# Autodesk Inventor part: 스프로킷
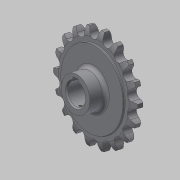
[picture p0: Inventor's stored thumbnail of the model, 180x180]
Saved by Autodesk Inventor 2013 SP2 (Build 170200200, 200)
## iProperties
Created: 2016-03
Part Number: 스프로킷
Material: 강철, 탄소
Document SubType Name: Modeling
Designer: mduedu
Density: 7.87 g/cm^3
Mass: 301.818 g
Surface Area: 124.882 cm^2
Volume: 38.3505 cm^3
Author: mduedu
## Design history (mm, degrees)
sketch "스케치1"
  geometry: L1 (0, 5)-(29.5, 5); L2 (29.5, 5)-(29.5, 4.1); L3 (30, 3.6)-(33.625, 3.6); L4 (40, 2)-(40, 0); L5 (40, 0)-(0, 0); L6 (0, 0)-(0, 5); L7 (0, -5)-(29.5, -5); L8 (29.5, -5)-(29.5, -4.1); L9 (30, -3.6)-(33.625, -3.6); L10 (40, -2)-(40, 0); L11 (0, 0)-(0, -5); A1 r 13.5 centre (33.625, -9.9) between (40, 2) and (33.625, 3.6); A2 r 13.5 centre (33.625, 9.9) between (33.625, -3.6) and (40, -2); A3 r 0.5 centre (30, 4.1) between (29.5, 4.1) and (30, 3.6); A4 r 0.5 centre (30, -4.1) between (30, -3.6) and (29.5, -4.1); 2 further points
  constraints: 22 end point, 8 point on circle, 6 symmetric about line, 5 tangent, 4 centre point, 4 parallel, 4 point on line, 1 equal radius, 1 horizontal, 1 perpendicular, 1 other
  dimensions: "d0" = 80 diameter of L4 L6; "d2" = 59 diameter of L2 L6; "d3" = 1.6 vertical distance of L4.start L3.end; "d4" = 3.6 distance from line of L4.end L3; "d5" = 5 distance between parallel lines of L5 L1; "d6" = 13.5 radius of A1; "d15" = 0.5 radius of A3
revolve "회전1" sketch "스케치1" stored, may be unused: angle "d7" = 90 deg
sketch "스케치2" dims "d8" = 65.2, "d11" = 80
  geometry: L1 (0, 0)-(0, 32.6); A1 r 36.57 centre (0, 0) between (-16.231, 32.771) and (0, 36.57); A2 r 3.97 centre (0, 36.57) between (-3.866, 35.665) and (0, 32.6); A3 r 12.7 centre (-16.231, 32.771) between (-3.866, 35.665) and (-5.534, 39.615); A4 r 12.7 centre (16.231, 32.771) between (5.534, 39.615) and (3.866, 35.665); A5 r 3.97 centre (0, 36.57) between (0, 32.6) and (3.866, 35.665); A6 r 40 centre (0, 0) between (5.534, 39.615) and (-5.534, 39.615); 2 further points
  constraints: 12 point on circle, 6 centre point, 4 coincident, 3 symmetric about line, 2 end point, 1 point on line, 1 tangent, 1 vertical, 1 vertical alignment, 7 other
  dimensions: "d10" = 73.14 diameter of A1; "d12" = 12.7 radius of A3
extrude "돌출1" cut sketch "스케치2" stored distance "d13" = 10; taper "d14" = 0 deg
sketch "스케치3"
  geometry: C1 r 13.5 at (0, 0); 1 further point
  constraints: 1 centre point, 1 coincident
  dimensions: "d19" = 27 diameter of C1
extrude "돌출2" join sketch "스케치3" distance "d20" = 13; taper "d21" = 0 deg
fillet "모깎기1" dims "d22" = 3
sketch "스케치4"
  geometry: L1 (-2.5, 0)-(2.5, 0); L2 (2.5, 0)-(2.5, 10.8); L3 (2.5, 10.8)-(-2.5, 10.8); L4 (-2.5, 10.8)-(-2.5, 0); C1 r 8.5 at (0, 0); 2 further points
  constraints: 8 end point, 2 coincident, 2 parallel, 1 centre point, 1 horizontal, 1 midpoint, 1 perpendicular
  dimensions: "d23" = 17 diameter of C1; "d25" = 5 distance of L2.end L3.end; "d26" = 10.8 distance of L1.end L2.end
extrude "돌출3" cut sketch "스케치4" stored distance "d27" = 8; taper "d28" = 0 deg
chamfer "모따기1" distance "d29" = 1; stored, may be unused: second distance "d30" = 2, angle "d31" = 45 deg
node "작업 평면1"
sketch "스케치5"
  geometry: L1 (13.5, 13)-(-13.5, 13) reference; 2 further points
  constraints: 1 vertical alignment
  dimensions: "d32" = 4 distance from line of point (0, 9) L1
hole "구멍1" sketch "스케치5" at (0, 9) diameter "d33" = 2.459; stored, may be unused: countersink angle "d37" = 90 deg, drill point angle "d39" = 118 deg; dims "d34" = 6, "d35" = 4, "d36" = 2, "d38" = 8
node "솔리드1"
pattern_circular "원형 패턴1" dims angle "d17" = 360 deg
